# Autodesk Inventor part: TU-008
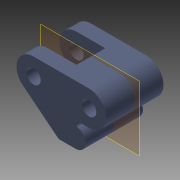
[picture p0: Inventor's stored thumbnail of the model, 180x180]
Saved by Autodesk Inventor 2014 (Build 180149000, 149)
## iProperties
Shininess: 64.0
Angle Display Precision: 2
Document Length Units: 11269
Document Angle Units: 11279
Document Time Units: 11290
Document Mass Units: 11286
Document Length Units Precision: 3
Document Angle Units Precision: 2
Created: 2002-07
Part Number: TU-008
Document SubType Name: Modeling
Designer: PN
Density: 1 g/cm^3
Description: Hinge
Mass: 25.6282 g
Surface Area: 85.6046 cm^2
Volume: 25.6282 cm^3
Material: Generic
Appearance: Rubber (Blue)
Density: 0.0
Volumn: 0.0
Area: 0.0
PropertySet Name: Model Information
Control State: 0
Master: False
Checked Out: False
LENGTH: 1.000 in
Author: PN
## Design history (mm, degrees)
sketch "Sketch1"
  geometry: L1 (31, 0)-(0, 0); L2 (14, -32.84)-(-5.582, -17.187); L3 (23.513, -32.84)-(14, -32.84); L4 (31, -19)-(25, -19); C1 r 4 at (0, -9.5); C2 r 4 at (31, -9.5); A1 r 9.5 centre (0, -9.5) between (0, 0) and (-5.582, -17.187); A2 r 5.5 centre (23.513, -27.34) between (23.513, -32.84) and (24.681, -21.966); A3 r 1.5 centre (25, -20.5) between (25, -19) and (24.681, -21.966); A4 r 9.5 centre (31, -9.5) between (31, -19) and (31, 0); 1 further point
  constraints: 8 end point, 8 point on circle, 7 tangent, 6 centre point, 2 coincident with centre, 2 parallel, 1 coincident, 1 equal radius, 1 horizontal
  dimensions: "d0" = 9.5 radius of A1; "d1" = 8 diameter of C1; "d2" = 31 distance of A4.centre A1.centre; "d3" = 1.5 radius of A3; "d4" = 5.5 radius of A2; "d6" = 9.51297 distance of L3.start L2.start; "d7" = 38.6376 deg angle of L3 L2; "d9" = 32.84023 distance between parallel lines of L3 L1; "d10" = 16.91036 distance from line of point (0, 0) L2
extrude "Extrusion1" new body sketch "Sketch1" stored distance "d11" = 32; taper "d12" = 0 deg
sketch "Sketch2"
  geometry: L1 (0, -32)-(0, 0) reference; L2 (-23.5, -32)-(-23.5, 0) reference; L3 (-23.5, -24)-(2, -24); L4 (2, -24)-(2, -8); L5 (2, -8)-(-23.5, -8); L6 (-23.5, -8)-(-23.5, -24); 1 further point
  constraints: 8 end point, 2 midpoint, 2 parallel, 1 horizontal, 1 perpendicular
  dimensions: "d13" = 2 distance between parallel lines of L4 L1; "d14" = 16 distance of L5.end L3.start
extrude "Extrusion2" cut sketch "Sketch2" stored distance "d15" = 32; taper "d16" = 0 deg
hole "Hole1" diameter "d19" = 8; stored, may be unused: countersink angle "d23" = 90 deg, drill point angle "d25" = 118 deg; dims "d17" = 10, "d18" = 10, "d20" = 6, "d21" = 4, "d22" = 2, "d24" = 8
hole "Hole2" diameter "d28" = 8; stored, may be unused: countersink angle "d32" = 90 deg, drill point angle "d34" = 118 deg; dims "d26" = 10, "d27" = 10, "d29" = 6, "d30" = 4, "d31" = 2, "d33" = 8
body "Solid1"
other parameters: "LENGTH" = 25.4 [user parameter]
